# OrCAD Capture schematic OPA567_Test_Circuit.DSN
size A; title: OPA567  Rail-to-Rail I/O, 2A POWER AMPLIFIER; rev: 1.1; note: Datasheet:  SBOS287A EVM: NA
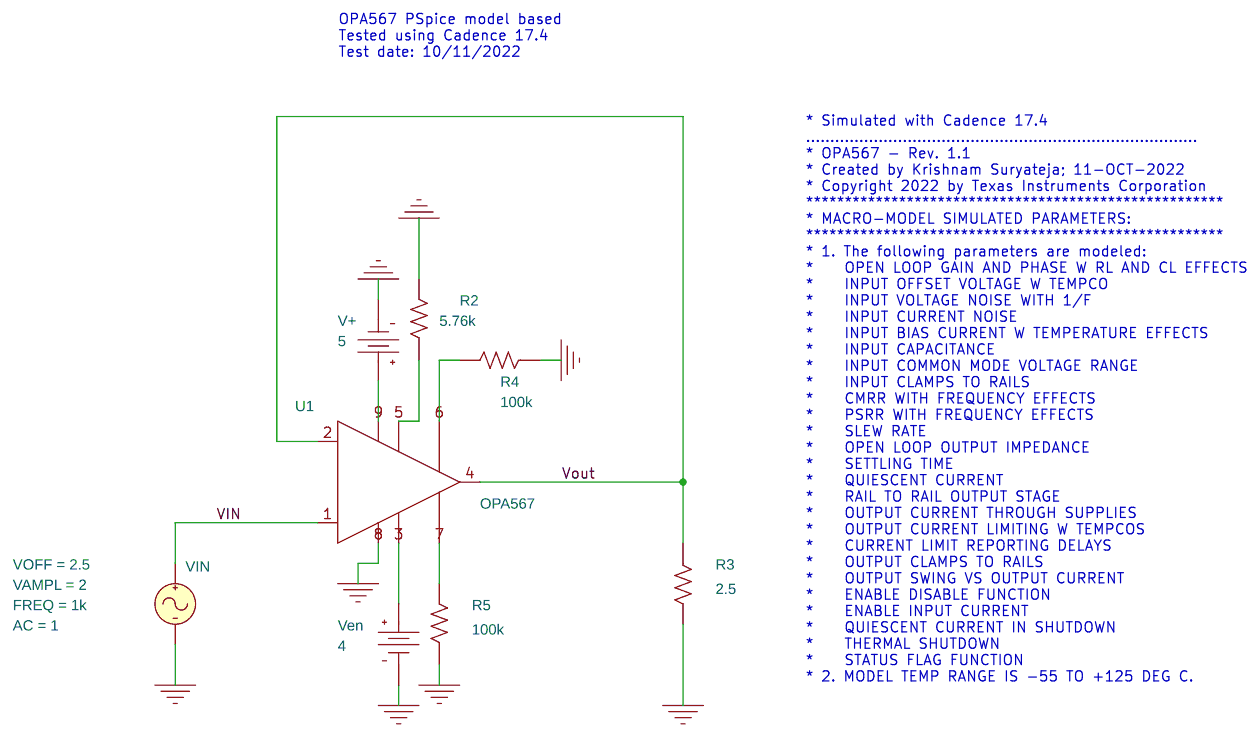
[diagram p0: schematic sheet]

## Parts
R2  5.76k  [AX/RC05]
R3  2.5  [AX/RC05]
R4  100k  [AX/RC05]
R5  100k  [AX/RC05]
U1  OPA567
V+  VDC
Ven  VDC
VIN  VSIN

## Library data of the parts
R2-R5 = R
U1 = OPA567
V+ = VDC: DC: 5
Ven = VDC: DC: 4
VIN = VSIN: AC: 1; DC: 2.5; FREQ: 1k; VAMPL: 2; VOFF: 2.5

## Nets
VIN: U1.1(+) VIN.1(+)
0: R2.2 R3.2 R4.1 R5.1 U1.8(V-) V+.1(-) Ven.1(-) VIN.2(-)
Vout: R3.1 U1.2(-) U1.4(OUT)
N14310671: R2.1 U1.5(ISET)
N14310795: U1.3(EN) Ven.0(+)
N14310801: R5.2 U1.7(TFLAG)
N14311262: U1.9(V+) V+.0(+)
N14312167: R4.2 U1.6(IFLAG)

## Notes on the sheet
- OPA567 PSpice model based
  Tested using Cadence 17.4
  Test date: 10/11/2022
- * Simulated with Cadence 17.4
  .................................................................................
  * OPA567 - Rev. 1.1
  * Created by Krishnam Suryateja; 11-OCT-2022
  * Copyright 2022 by Texas Instruments Corporation
  ******************************************************
  * MACRO-MODEL SIMULATED PARAMETERS:
  ******************************************************
  * 1. The following parameters are modeled:
  *    OPEN LOOP GAIN AND PHASE W RL AND CL EFFECTS
  *    INPUT OFFSET VOLTAGE W TEMPCO
  *    INPUT VOLTAGE NOISE WITH 1/F
  *    INPUT CURRENT NOISE
  *    INPUT BIAS CURRENT W TEMPERATURE EFFECTS
  *    INPUT CAPACITANCE
  *    INPUT COMMON MODE VOLTAGE RANGE
  *    INPUT CLAMPS TO RAILS
  *    CMRR WITH FREQUENCY EFFECTS
  *    PSRR WITH FREQUENCY EFFECTS
  *    SLEW RATE
  *    OPEN LOOP OUTPUT IMPEDANCE
  *    SETTLING TIME
  *    QUIESCENT CURRENT
  *    RAIL TO RAIL OUTPUT STAGE
  *    OUTPUT CURRENT THROUGH SUPPLIES
  *    OUTPUT CURRENT LIMITING W TEMPCOS
  *    CURRENT LIMIT REPORTING DELAYS
  *    OUTPUT CLAMPS TO RAILS
  *    OUTPUT SWING VS OUTPUT CURRENT
  *    ENABLE DISABLE FUNCTION
  *    ENABLE INPUT CURRENT
  *    QUIESCENT CURRENT IN SHUTDOWN
  *    THERMAL SHUTDOWN
  *    STATUS FLAG FUNCTION
  * 2. MODEL TEMP RANGE IS -55 TO +125 DEG C.
